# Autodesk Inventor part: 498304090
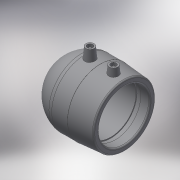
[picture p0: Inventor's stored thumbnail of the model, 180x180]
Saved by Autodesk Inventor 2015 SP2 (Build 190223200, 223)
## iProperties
Created: 2017-06
Part Number: 498304090
Material: Generic
Description: PLASSON MONOLITHIC WELD END CAP FOR BALLON SADDLE 90
Document SubType Name: Modeling
Designer: Кирилл
Density: 1 g/cm^3
Appearance: Default
Author: Кирилл
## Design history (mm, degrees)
derived "498304.ipt"
feature "Solid1::498304.ipt"
tag "TaggingFeature1"
body "Solid1"
other parameters: "d0" = 123, "d1" = 1, "d2" = 71, "d4" = 117, "d5" = 12.3, "d7" = 3.51, "d8" = 43.05, "d10" = 2.34, "d11" = 24.6, "d12" = 168 deg, "d13" = 8.2, "d15" = 77, "d16" = 15, "d17" = 61.5, "d18" = 1, "d20" = 5 deg, "d21" = 69.3, "d22" = 15, "d23" = 1, "d24" = 103.32, "d26" = 5 deg, "d27" = 4, "d29" = 14, "d30" = 0, "d31" = 4, "d33" = 14, "d34" = 0, "d37" = 81, "d38" = 71, "d39" = 81.65, "d40" = 93.6, "d41" = 4.5, "d42" = 0, "d44" = 360 deg, "d46" = 3, "d47" = 0, "d48" = 3, "d49" = 0, "L_" = 123, "L_1" = 71, "D_" = 117, "A_" = 77, "d_2" = 12
